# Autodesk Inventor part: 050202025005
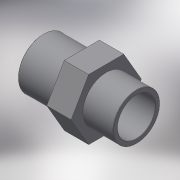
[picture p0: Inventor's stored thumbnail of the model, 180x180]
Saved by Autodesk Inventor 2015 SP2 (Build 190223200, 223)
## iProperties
Created: 2017-10
Part Number: 050202025005
Material: Generic
Description: PLASSON REDUCER THR-CEM PVC 25(20)1/2"F
Document SubType Name: Modeling
Designer: KIM
Density: 1 g/cm^3
Appearance: Default
Author: KIM
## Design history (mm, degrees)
derived "050202.ipt"
feature "Solid1::050202.ipt"
tag "TaggingFeature1"
body "Solid1"
other parameters: "d0" = 46, "d3" = 18.631, "d4" = 18, "d6" = 17, "d7" = 25, "d8" = 23, "d13" = 0, "d14" = 0.2, "d16" = 12, "d17" = 19, "d18" = 20.4, "G_" = 18.631, "B_" = 12, "L_" = 19, "lt_" = 17, "H_" = 46, "D_" = 25
